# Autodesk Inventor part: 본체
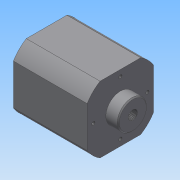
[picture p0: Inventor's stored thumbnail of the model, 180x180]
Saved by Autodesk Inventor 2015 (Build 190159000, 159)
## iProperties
Created: 2020-02
Part Number: 본체
Material: 일반
Document SubType Name: Modeling
Designer: user
Density: 1 g/cm^3
Appearance: 기본값
Author: user
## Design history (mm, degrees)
sketch "스케치1"
  geometry: L1 (-19.551, -32)-(19.551, -32); L2 (32, -19.551)-(32, 19.551); L3 (19.551, 32)-(-19.551, 32); L4 (-32, 19.551)-(-32, -19.551); L5 (-32.2, -33.191)-(30.823, 31.771); L6 (30.823, -32.229)-(-25.919, 27.101); A1 r 37.5 centre (0, 0) between (-19.551, 32) and (-32, 19.551); A2 r 37.5 centre (0, 0) between (-32, -19.551) and (-19.551, -32); A3 r 37.5 centre (0, 0) between (19.551, -32) and (32, -19.551); A4 r 37.5 centre (0, 0) between (32, 19.551) and (19.551, 32); 1 further point
  constraints: 12 end point, 9 point on circle, 4 centre point, 2 parallel, 2 point on line, 1 coincident, 1 horizontal, 1 perpendicular
  dimensions: "d1" = 64 distance of L6.start L5.end
extrude "돌출1" new body sketch "스케치1" distance "d3" = 71; taper "d4" = 0 deg
sketch "스케치2"
  geometry: C1 r 14 at (0, 0); A1 r 37.5 centre (0, 0) between (-32, -19.551) and (-19.551, -32) reference
  constraints: 1 centre point, 1 coincident
  dimensions: "d6" = 28 diameter of C1
extrude "돌출2" join sketch "스케치2" distance "d7" = 12; taper "d8" = 0 deg
chamfer "모따기1" distance "d9" = 1; stored, may be unused: second distance "d10" = 2, angle "d11" = 45 deg
hole "구멍1" diameter "d14" = 8.917; stored, may be unused: countersink angle "d18" = 15 deg, drill point angle "d20" = 118 deg; dims "d12" = 10, "d13" = 10, "d15" = 14, "d16" = 40, "d17" = 2, "d19" = 17
hole "구멍2" diameter "d23" = 4; stored, may be unused: countersink angle "d27" = 15 deg, drill point angle "d29" = 118 deg; dims "d21" = 10, "d22" = 10, "d24" = 14, "d25" = 40, "d26" = 2, "d28" = 100
hole "구멍3" diameter "d32" = 40; stored, may be unused: countersink angle "d36" = 15 deg, drill point angle "d38" = 118 deg; dims "d30" = 10, "d31" = 10, "d33" = 14, "d34" = 40, "d35" = 2, "d37" = 62
chamfer "모따기2" distance "d39" = 1.8; stored, may be unused: second distance "d40" = 2, angle "d41" = 15 deg
sketch "스케치3" dims "d42" = 52
  geometry: L1 (0, 0)-(0, 34.877); C1 r 2.623 at (0, 26); A1 r 37.5 centre (0, 0) between (-32, -19.551) and (-19.551, -32) reference
  constraints: 2 end point, 1 centre point, 1 coincident, 1 point on line, 1 vertical, 1 vertical alignment, 2 other
hole "구멍4" sketch "스케치3" at (0, 26) diameter "d43" = 3.242; stored, may be unused: countersink angle "d47" = 15 deg, drill point angle "d49" = 118 deg; dims "d44" = 10, "d45" = 40, "d46" = 2, "d48" = 12
sketch "스케치4" dims "d53" = 52
  geometry: L1 (0, 0)-(0, -38.592); C1 r 20.482 at (0, 0) reference; C2 r 2.624 at (0, -26)
  constraints: 2 end point, 1 centre point, 1 coincident, 1 point on line, 1 vertical, 1 vertical alignment, 2 other
hole "구멍5" sketch "스케치4" at (0, -26) diameter "d54" = 3.242; stored, may be unused: countersink angle "d58" = 15 deg, drill point angle "d60" = 118 deg; dims "d55" = 10, "d56" = 40, "d57" = 2, "d59" = 12
sketch "스케치5"
  geometry: L1 (0, 39.102)-(0, 0) reference; L2 (0, 0)-(71, 0) reference; L3 (71, 39.102)-(71, 0) reference; L4 (0, 39.102)-(71, 39.102) reference; L5 (17, 17)-(17, 22.102); L6 (17, 22.102)-(54, 22.102); L7 (54, 22.102)-(54, 17); L8 (54, 17)-(17, 17); L9 (0, 19.551)-(32.17, 19.551); C1 r 1.388 at (17, 19.551)
  constraints: 10 end point, 1 centre point, 1 horizontal, 1 midpoint, 1 point on line, 3 other
  dimensions: "d64" = 17 distance between parallel lines of L1 L5
hole "구멍6" sketch "스케치5" at (17, 19.551) diameter "d65" = 8.917; stored, may be unused: countersink angle "d69" = 15 deg, drill point angle "d71" = 118 deg; dims "d66" = 6, "d67" = 40, "d68" = 2, "d70" = 9
hole "구멍7" diameter "d74" = 4; stored, may be unused: countersink angle "d78" = 15 deg, drill point angle "d80" = 0 deg; dims "d72" = 10, "d73" = 10, "d75" = 6, "d76" = 40, "d77" = 2, "d79" = 30
sketch "스케치6"
  geometry: L1 (71, 39.102)-(71, 0) reference; L2 (71, -12.449)-(71, 0) reference; L3 (71, 19.551)-(0, 19.551); L4 (51, 19.551)-(51, -15.129); 1 further point
  constraints: 4 end point, 1 coincident, 1 horizontal, 1 midpoint, 1 point on line, 1 vertical, 1 other
feature "엠보싱1" sketch "스케치6" dims "d1" = 64, "d17" = 2, "d82" = 0.5, "d83" = 0
node "솔리드1"
pattern_circular "원형 패턴1" dims angle "d51" = 360 deg
pattern_circular "원형 패턴2" dims angle "d62" = 360 deg
other parameters: "d2" = 75
